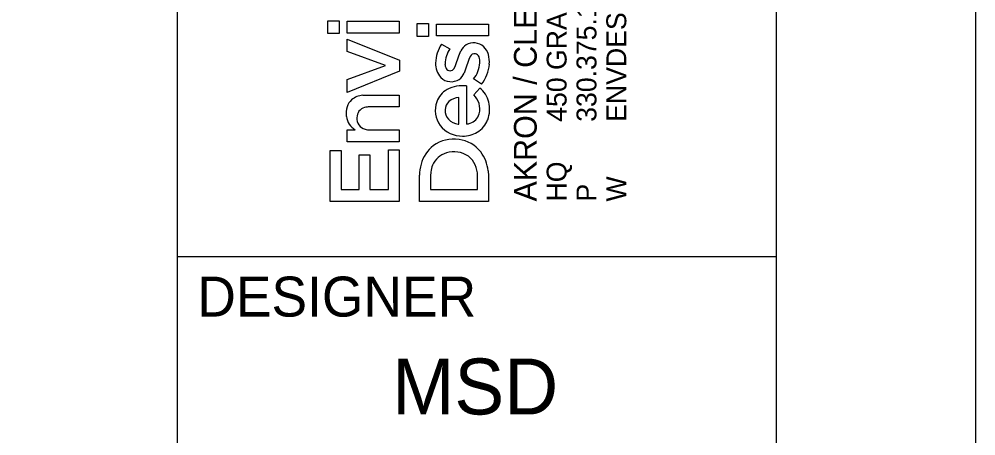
# Model space of a CAD drawing. Extents: x -4.3 to 34, y -0.8 to 22.
# Drawn here: x 31.604 to 34, y 2.552 to 3.594 of the extents above; entities that cross this region are included whole.
import ezdxf

# ---------------------------------------------------------------- set-up
doc = ezdxf.new("R2010")
doc.units = 0
for name, color, linetype in [('SH_Border', 7, 'Continuous'), ('SH_Cut_Line', 7, 'Continuous'), ('SH_Data', 7, 'Continuous')]:
    doc.layers.add(name, color=color, linetype=linetype)

msp = doc.modelspace()

# ---------------------------------------------------------------- linework, layer by layer
at = {"layer": 'SH_Border'}
for p, q in [((32, 0.5), (32, 21.5)), ((32, 3), (33.5, 3))]:
    msp.add_line(p, q, dxfattribs=at)
msp.add_lwpolyline([(1.5, 21.5), (33.5, 21.5), (33.5, 0.5), (1.5, 0.5)], close=True, dxfattribs=at)
at = {"layer": 'SH_Cut_Line'}
msp.add_lwpolyline([(0, 0), (34, 0), (34, 22), (0, 22)], close=True, dxfattribs=at)
at = {"layer": 'SH_Data'}
for p, q in [((32.3771, 3.5582), (32.3771, 3.5903)), ((32.3771, 3.5903), (32.4054, 3.5903)), ((32.4054, 3.5903), (32.4054, 3.5582)), ((32.4254, 3.5594), (32.4254, 3.5893)), ((32.4254, 3.5893), (32.5557, 3.5893)), ((32.5557, 3.5893), (32.5557, 3.5594)), ((32.6005, 3.5511), (32.6005, 3.5832)), ((32.6005, 3.5832), (32.6289, 3.5832)), ((32.6289, 3.5832), (32.6289, 3.5511)), ((32.6489, 3.5523), (32.6489, 3.5822)), ((32.6489, 3.5822), (32.7792, 3.5822)), ((32.7792, 3.5822), (32.7792, 3.5523)), ((32.4054, 3.5582), (32.3771, 3.5582)), ((32.5557, 3.5594), (32.4254, 3.5594)), ((32.6289, 3.5511), (32.6005, 3.5511)), ((32.7792, 3.5523), (32.6489, 3.5523)), ((32.4254, 3.5133), (32.4254, 3.5446)), ((32.4254, 3.5446), (32.5567, 3.4913)), ((32.6615, 3.5321), (32.6827, 3.5203)), ((32.5212, 3.478), (32.4254, 3.5133)), ((32.6967, 3.4787), (32.7048, 3.5026)), ((32.7048, 3.5026), (32.7104, 3.5153)), ((32.7334, 3.501), (32.7298, 3.4933)), ((32.4254, 3.4429), (32.5212, 3.478)), ((32.5567, 3.4913), (32.5567, 3.4644)), ((32.693, 3.4712), (32.6967, 3.4787)), ((32.7298, 3.4933), (32.7221, 3.4688)), ((32.5567, 3.4644), (32.4254, 3.4109)), ((32.7221, 3.4688), (32.7182, 3.4592)), ((32.4254, 3.4109), (32.4254, 3.4429)), ((32.7245, 3.4275), (32.7246, 3.3319)), ((32.7621, 3.4314), (32.742, 3.4447)), ((32.4644, 3.404), (32.4729, 3.4044)), ((32.4729, 3.4044), (32.5557, 3.4044)), ((32.5557, 3.4044), (32.5557, 3.3746)), ((32.7423, 3.4046), (32.7577, 3.422)), ((32.7049, 3.3318), (32.7049, 3.3983)), ((32.5557, 3.3746), (32.4814, 3.3746)), ((32.7036, 3.3317), (32.7049, 3.3318)), ((32.4254, 3.2875), (32.4254, 3.3173)), ((32.4254, 3.3173), (32.4455, 3.3173)), ((32.4822, 3.3173), (32.5557, 3.3173)), ((32.5557, 3.3173), (32.5557, 3.2876)), ((32.5557, 3.2876), (32.4254, 3.2875)), ((32.383, 3.1379), (32.383, 3.266)), ((32.383, 3.266), (32.4101, 3.266)), ((32.4101, 3.266), (32.4101, 3.1683)), ((32.5286, 3.1683), (32.5286, 3.2672)), ((32.5286, 3.2672), (32.5557, 3.2672)), ((32.5557, 3.2672), (32.5557, 3.1379)), ((32.455, 3.1683), (32.455, 3.2549)), ((32.455, 3.2549), (32.4822, 3.2549)), ((32.4822, 3.2549), (32.4822, 3.1683)), ((32.6347, 3.2118), (32.6341, 3.2023)), ((32.7785, 3.215), (32.7792, 3.2021)), ((32.6064, 3.138), (32.6064, 3.204)), ((32.6341, 3.2023), (32.6341, 3.1684)), ((32.7515, 3.1683), (32.7515, 3.2024)), ((32.7792, 3.2021), (32.7792, 3.138)), ((32.4101, 3.1683), (32.455, 3.1683)), ((32.4822, 3.1683), (32.5286, 3.1683)), ((32.6341, 3.1684), (32.7515, 3.1683)), ((32.5557, 3.1379), (32.383, 3.1379)), ((32.7792, 3.138), (32.6064, 3.138))]:
    msp.add_line(p, q, dxfattribs=at)
for points in [[(32.3771, 3.5582), (32.3771, 3.5903), (32.4054, 3.5903), (32.4054, 3.5582)], [(32.4254, 3.5594), (32.4254, 3.5893), (32.5557, 3.5893), (32.5557, 3.5594)], [(32.6005, 3.5511), (32.6005, 3.5832), (32.6289, 3.5832), (32.6289, 3.5511)], [(32.6489, 3.5523), (32.6489, 3.5822), (32.7792, 3.5822), (32.7792, 3.5523)], [(32.4254, 3.4109), (32.4254, 3.4429), (32.5212, 3.478), (32.4254, 3.5133), (32.4254, 3.5446), (32.5567, 3.4913), (32.5567, 3.4644)], [(32.383, 3.1379), (32.383, 3.266), (32.4101, 3.266), (32.4101, 3.1683), (32.455, 3.1683), (32.455, 3.2549), (32.4822, 3.2549), (32.4822, 3.1683), (32.5286, 3.1683), (32.5286, 3.2672), (32.5557, 3.2672), (32.5557, 3.1379)]]:
    msp.add_lwpolyline(points, close=True, dxfattribs=at)
for points in [[(32.6615, 3.5321), (32.6827, 3.5203)], [(32.693, 3.4712), (32.6967, 3.4787), (32.7048, 3.5026), (32.7104, 3.5153)], [(32.7334, 3.501), (32.7298, 3.4933), (32.7221, 3.4688), (32.7182, 3.4592)], [(32.7245, 3.4275), (32.7246, 3.3319)], [(32.7621, 3.4314), (32.742, 3.4447)], [(32.4644, 3.404), (32.4729, 3.4044), (32.5557, 3.4044), (32.5557, 3.3746), (32.4814, 3.3746)], [(32.7423, 3.4046), (32.7577, 3.422)], [(32.7036, 3.3317), (32.7049, 3.3318), (32.7049, 3.3983)], [(32.4254, 3.2875), (32.4254, 3.3173), (32.4455, 3.3173)], [(32.4822, 3.3173), (32.5557, 3.3173), (32.5557, 3.2876), (32.4254, 3.2875)], [(32.7785, 3.215), (32.7792, 3.2021), (32.7792, 3.138), (32.6064, 3.138)], [(32.6347, 3.2118), (32.6341, 3.2023), (32.6341, 3.1684), (32.7515, 3.1683), (32.7515, 3.2024)], [(32.6064, 3.138), (32.6064, 3.204)]]:
    msp.add_lwpolyline(points, dxfattribs=at)
for centre, radius, start, end in [((32.7364, 3.4826), 0.0897, 146.531, 178.7571), ((32.7364, 3.4826), 0.0897, 146.531, 178.7571), ((32.7466, 3.4971), 0.0405, 125.5118, 153.4159), ((32.7466, 3.4971), 0.0405, 125.5118, 153.4159), ((32.7406, 3.5026), 0.0326, 80.1719, 122.5197), ((32.7406, 3.5026), 0.0326, 80.1719, 122.5197), ((32.7428, 3.4982), 0.0367, 47.7934, 84.6892), ((32.7428, 3.4982), 0.0367, 47.7934, 84.6892), ((32.7379, 3.4946), 0.0427, 14.9966, 46.2063), ((32.7379, 3.4946), 0.0427, 14.9966, 46.2063), ((32.7452, 3.4789), 0.0749, 146.5112, 176.9101), ((32.7452, 3.4789), 0.0749, 146.5112, 176.9101), ((32.7438, 3.4963), 0.0114, 76.6609, 155.7053), ((32.7438, 3.4963), 0.0114, 76.6609, 155.7053), ((32.744, 3.4951), 0.0126, 21.5098, 78.5262), ((32.744, 3.4951), 0.0126, 21.5098, 78.5262), ((32.7259, 3.4877), 0.0321, 354.5726, 22.068), ((32.7259, 3.4877), 0.0321, 354.5726, 22.068), ((32.7104, 3.4867), 0.0712, 355.8306, 15.3914), ((32.7104, 3.4867), 0.0712, 355.8306, 15.3914), ((32.6967, 3.4824), 0.0501, 177.5366, 222.7932), ((32.6967, 3.4824), 0.0501, 177.5366, 222.7932), ((32.6931, 3.4823), 0.0228, 178.4747, 211.0868), ((32.6931, 3.4823), 0.0228, 178.4747, 211.0868), ((32.6825, 3.4915), 0.0757, 321.811, 354.7969), ((32.6825, 3.4915), 0.0757, 321.811, 354.7969), ((32.6895, 3.4882), 0.0922, 321.9777, 355.8738), ((32.6895, 3.4882), 0.0922, 321.9777, 355.8738), ((32.6833, 3.4767), 0.0115, 212.2368, 268.3777), ((32.6833, 3.4767), 0.0115, 212.2368, 268.3777), ((32.6834, 3.4759), 0.0107, 267.716, 333.7337), ((32.6834, 3.4759), 0.0107, 267.716, 333.7337), ((32.681, 3.4758), 0.0408, 308.0877, 335.9874), ((32.681, 3.4758), 0.0408, 308.0877, 335.9874), ((32.686, 3.4753), 0.0375, 225.9854, 302.4797), ((32.686, 3.4753), 0.0375, 225.9854, 302.4797), ((32.7152, 3.3441), 0.0838, 83.615, 118.2876), ((32.7152, 3.3441), 0.0838, 83.615, 118.2876), ((32.4687, 3.3543), 0.0499, 94.9696, 130.2225), ((32.4687, 3.3543), 0.0499, 94.9696, 130.2225), ((32.7024, 3.3691), 0.0558, 118.8308, 160.6244), ((32.7024, 3.3691), 0.0558, 118.8308, 160.6244), ((32.7038, 3.3656), 0.0549, 19.0357, 45.4406), ((32.7038, 3.3656), 0.0549, 19.0357, 45.4406), ((32.7174, 3.3717), 0.0644, 13.5336, 51.3615), ((32.7174, 3.3717), 0.0644, 13.5336, 51.3615), ((32.4635, 3.3626), 0.0402, 132.2219, 161.6818), ((32.4635, 3.3626), 0.0402, 132.2219, 161.6818), ((32.7104, 3.3661), 0.0644, 160.5201, 215.7831), ((32.7104, 3.3661), 0.0644, 160.5201, 215.7831), ((32.7005, 3.3663), 0.0298, 132.9851, 177.179), ((32.7005, 3.3663), 0.0298, 132.9851, 177.179), ((32.7079, 3.3561), 0.0424, 94.008, 130.8817), ((32.7079, 3.3561), 0.0424, 94.008, 130.8817), ((32.7107, 3.3697), 0.047, 344.6059, 17.007), ((32.7107, 3.3697), 0.047, 344.6059, 17.007), ((32.7064, 3.3692), 0.0758, 339.3542, 13.3785), ((32.7064, 3.3692), 0.0758, 339.3542, 13.3785), ((32.4787, 3.3582), 0.056, 162.2736, 187.7919), ((32.4787, 3.3582), 0.056, 162.2736, 187.7919), ((32.4748, 3.3487), 0.025, 103.6865, 182.2187), ((32.4748, 3.3487), 0.025, 103.6865, 182.2187), ((32.4811, 3.3286), 0.046, 89.6049, 105.3284), ((32.4811, 3.3286), 0.046, 89.6049, 105.3284), ((32.7017, 3.365), 0.0311, 175.0013, 223.283), ((32.7017, 3.365), 0.0311, 175.0013, 223.283), ((32.7224, 3.3671), 0.035, 288.0077, 343.5508), ((32.7224, 3.3671), 0.035, 288.0077, 343.5508), ((32.4703, 3.358), 0.0476, 188.962, 238.7037), ((32.4703, 3.358), 0.0476, 188.962, 238.7037), ((32.4773, 3.3456), 0.0276, 175.5854, 255.1439), ((32.4773, 3.3456), 0.0276, 175.5854, 255.1439), ((32.7089, 3.3736), 0.0423, 225.0619, 262.7974), ((32.7089, 3.3736), 0.0423, 225.0619, 262.7974), ((32.7247, 3.3522), 0.0202, 269.7003, 294.8711), ((32.7247, 3.3522), 0.0202, 269.7003, 294.8711), ((32.7189, 3.3652), 0.0626, 300.9427, 338.7323), ((32.7189, 3.3652), 0.0626, 300.9427, 338.7323), ((32.4818, 3.3595), 0.0422, 254.0916, 270.5284), ((32.4818, 3.3595), 0.0422, 254.0916, 270.5284), ((32.7125, 3.3705), 0.0687, 217.7452, 271.6543), ((32.7125, 3.3705), 0.0687, 217.7452, 271.6543), ((32.7155, 3.3724), 0.0706, 269.2048, 300.3341), ((32.7155, 3.3724), 0.0706, 269.2048, 300.3341), ((32.6923, 3.2079), 0.0864, 81.194, 125.9984), ((32.6923, 3.2079), 0.0864, 81.194, 125.9984), ((32.6946, 3.2113), 0.0827, 37.8521, 82.402), ((32.6946, 3.2113), 0.0827, 37.8521, 82.402), ((32.6939, 3.2089), 0.0865, 127.2362, 165.148), ((32.6939, 3.2089), 0.0865, 127.2362, 165.148), ((32.6889, 3.2078), 0.054, 106.1881, 157.3861), ((32.6889, 3.2078), 0.054, 106.1881, 157.3861), ((32.6928, 3.1986), 0.0639, 55.6727, 107.2093), ((32.6928, 3.1986), 0.0639, 55.6727, 107.2093), ((32.6859, 3.2057), 0.0931, 5.7333, 37.304), ((32.6859, 3.2057), 0.0931, 5.7333, 37.304), ((32.6929, 3.205), 0.0587, 357.4662, 52.2665), ((32.6929, 3.205), 0.0587, 357.4662, 52.2665), ((32.7143, 3.2028), 0.1078, 164.7861, 179.3704), ((32.7143, 3.2028), 0.1078, 164.7861, 179.3704), ((32.6983, 3.2039), 0.0641, 157.3571, 172.9275), ((32.6983, 3.2039), 0.0641, 157.3571, 172.9275)]:
    msp.add_arc(centre, radius, start, end, dxfattribs=at)

# ---------------------------------------------------------------- texts
for s, height, p in [('450 GRANT ST., AKRON, OH  44311', 0.049846, (32.9749, 3.3374)), ('AKRON / CLEVELAND / COLUMBUS', 0.056969, (32.9001, 3.138)), ('ENVDESIGNGROUP.COM', 0.049846, (33.1244, 3.3374)), ('330.375.1390', 0.049846, (33.0497, 3.3374)), ('HQ ', 0.04985, (32.9749, 3.138)), ('W', 0.0498, (33.1244, 3.138)), ('P', 0.0498, (33.0497, 3.138))]:
    msp.add_text(s, height=height, rotation=90, dxfattribs=at).set_placement(p)
for s, height, p in [('DESIGNER', 0.1, (32.05, 2.85)), ('MSD', 0.14, (32.5379, 2.605))]:
    msp.add_text(s, height=height, dxfattribs=at).set_placement(p)

doc.saveas('drawing.dxf')
